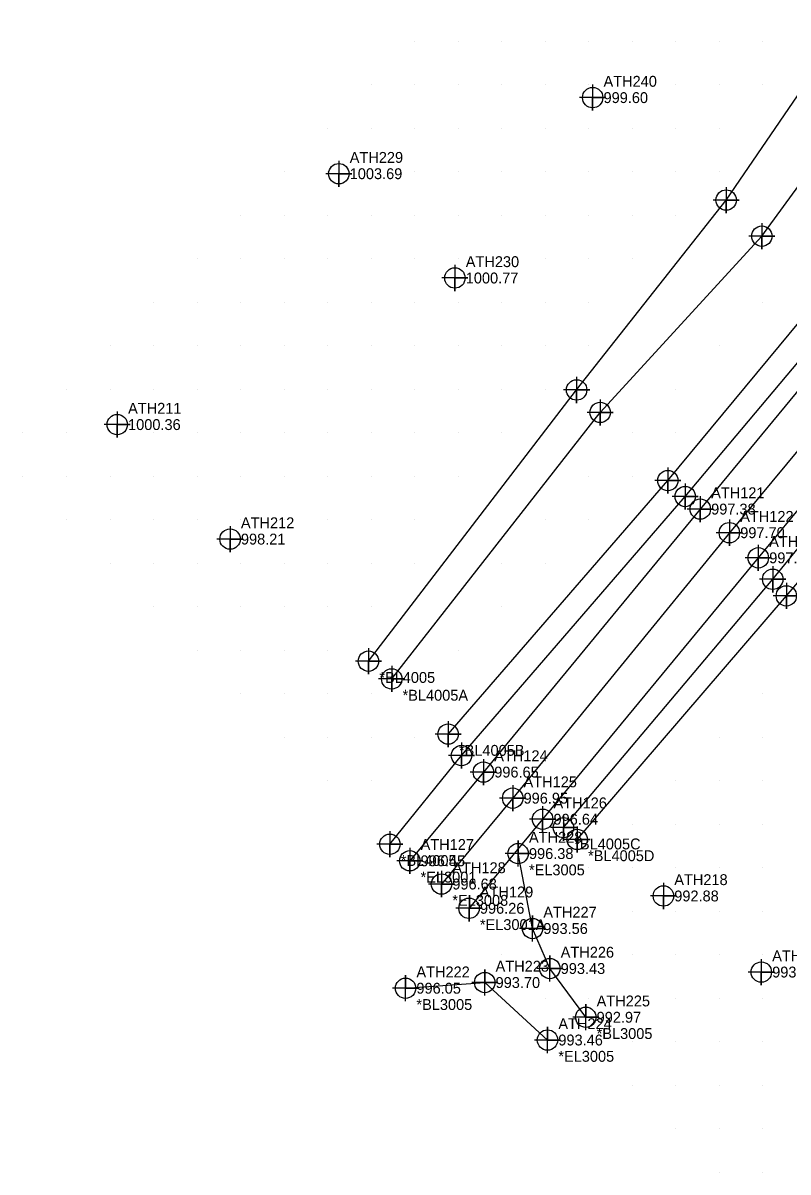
# Model space of a CAD drawing. Extents: x 1116680 to 1117499, y 661040 to 661703.
# Drawn here: x 1116680 to 1116855.8, y 661040 to 661304.2 of the extents above; entities that cross this region are included whole.
import ezdxf

# ---------------------------------------------------------------- set-up
doc = ezdxf.new("R2010")
doc.units = 0
for name, color, linetype in [('Exist DTM Breakline', 7, 'Continuous'), ('Exist DTM Breakline Cogo Comment', 7, 'Continuous'), ('Exist DTM Breakline Cogo Point CELL', 7, 'Continuous'), ('Exist DTM Crownline', 7, 'Continuous'), ('Exist DTM Crownline Cogo Comment', 7, 'Continuous'), ('Exist DTM Crownline Cogo Elevation', 7, 'Continuous'), ('Exist DTM Crownline Cogo Number', 7, 'Continuous'), ('Exist DTM Crownline Cogo Point CELL', 7, 'Continuous'), ('Exist DTM QL2 LIDAR Elevation Point', 7, 'Continuous'), ('Exist DTM Regular Point CELL', 7, 'Continuous'), ('Exist DTM Regular Point Cogo Elevation', 7, 'Continuous'), ('Exist DTM Regular Point Cogo Number', 7, 'Continuous'), ('Exist Roads EOP', 7, 'Continuous'), ('Exist Roads EOP Cogo Comment', 7, 'Continuous'), ('Exist Roads EOP Cogo Elevation', 7, 'Continuous'), ('Exist Roads EOP Cogo Number', 7, 'Continuous'), ('Exist Roads EOP Cogo Point CELL', 7, 'Continuous'), ('Exist Roads Soil', 7, 'Continuous'), ('Exist Roads Soil Cogo Comment', 7, 'Continuous'), ('Exist Roads Soil Cogo Elevation', 7, 'Continuous'), ('Exist Roads Soil Cogo Number', 7, 'Continuous'), ('Exist Roads Soil Cogo Point CELL', 7, 'Continuous')]:
    doc.layers.add(name, color=color, linetype=linetype)

msp = doc.modelspace()

# ---------------------------------------------------------------- linework, layer by layer
at = {"layer": 'Exist DTM Breakline'}
for points in [[(1116759.405, 661157.47), (1116807.255, 661219.832), (1116841.622, 661263.499), (1116875.544, 661313.217), (1116917.082, 661359.208), (1116949.523, 661400.365), (1116973.082, 661430.897), (1117008.611, 661472.228)], [(1116764.746, 661153.381), (1116812.662, 661214.66), (1116849.832, 661255.197), (1116886.132, 661304.973), (1116923.093, 661353.534), (1116959.436, 661397.157), (1116983.43, 661423.245), (1117016.608, 661461.344)], [(1116777.711, 661140.704), (1116828.227, 661198.994), (1116863.907, 661242.056), (1116901.537, 661293.371), (1116942.909, 661337.866), (1116986.207, 661371.481), (1117014.804, 661386.644), (1117027.371, 661386.959)], [(1116764.336, 661115.367), (1116780.79, 661135.76), (1116832.216, 661195.325), (1116868.599, 661238.611), (1116907.746, 661286.411), (1116949.649, 661334.962), (1116977.116, 661358.387), (1117017.083, 661374.758), (1117030.676, 661371.171)], [(1116804.214, 661119.184), (1116852.32, 661176.293), (1116889.45, 661221.661), (1116930.482, 661266.919), (1116979.857, 661313.491), (1117005.659, 661333.608)], [(1116807.384, 661116.479), (1116855.455, 661172.483), (1116887.171, 661209.743), (1116908.403, 661194.399), (1116931.527, 661183.283)]]:
    msp.add_lwpolyline(points, dxfattribs=at)
at = {"layer": 'Exist DTM Breakline Cogo Point CELL'}
for points in [[(1116841.622, 661266.499), (1116841.622, 661260.499), (1116841.622, 661263.499), (1116844.622, 661263.499), (1116838.622, 661263.499)], [(1116849.832, 661258.197), (1116849.832, 661252.197), (1116849.832, 661255.197), (1116852.832, 661255.197), (1116846.832, 661255.197)], [(1116807.255, 661222.832), (1116807.255, 661216.832), (1116807.255, 661219.832), (1116810.255, 661219.832), (1116804.255, 661219.832)], [(1116812.662, 661217.66), (1116812.662, 661211.66), (1116812.662, 661214.66), (1116815.662, 661214.66), (1116809.662, 661214.66)], [(1116828.227, 661201.994), (1116828.227, 661195.994), (1116828.227, 661198.994), (1116831.227, 661198.994), (1116825.227, 661198.994)], [(1116832.216, 661198.325), (1116832.216, 661192.325), (1116832.216, 661195.325), (1116835.216, 661195.325), (1116829.216, 661195.325)], [(1116852.32, 661179.293), (1116852.32, 661173.293), (1116852.32, 661176.293), (1116855.32, 661176.293), (1116849.32, 661176.293)], [(1116855.455, 661175.483), (1116855.455, 661169.483), (1116855.455, 661172.483), (1116858.455, 661172.483), (1116852.455, 661172.483)], [(1116759.405, 661160.47), (1116759.405, 661154.47), (1116759.405, 661157.47), (1116762.405, 661157.47), (1116756.405, 661157.47)], [(1116764.746, 661156.381), (1116764.746, 661150.381), (1116764.746, 661153.381), (1116767.746, 661153.381), (1116761.746, 661153.381)], [(1116777.711, 661143.704), (1116777.711, 661137.704), (1116777.711, 661140.704), (1116780.711, 661140.704), (1116774.711, 661140.704)], [(1116780.79, 661138.76), (1116780.79, 661132.76), (1116780.79, 661135.76), (1116783.79, 661135.76), (1116777.79, 661135.76)], [(1116804.214, 661122.184), (1116804.214, 661116.184), (1116804.214, 661119.184), (1116807.214, 661119.184), (1116801.214, 661119.184)], [(1116764.336, 661118.367), (1116764.336, 661112.367), (1116764.336, 661115.367), (1116767.336, 661115.367), (1116761.336, 661115.367)], [(1116807.384, 661119.479), (1116807.384, 661113.479), (1116807.384, 661116.479), (1116810.384, 661116.479), (1116804.384, 661116.479)]]:
    msp.add_lwpolyline(points, dxfattribs=at)
for centre in [(1116841.622, 661263.499), (1116849.832, 661255.197), (1116807.255, 661219.832), (1116812.662, 661214.66), (1116828.227, 661198.994), (1116832.216, 661195.325), (1116852.32, 661176.293), (1116855.455, 661172.483), (1116759.405, 661157.47), (1116764.746, 661153.381), (1116777.711, 661140.704), (1116780.79, 661135.76), (1116804.214, 661119.184), (1116764.336, 661115.367), (1116807.384, 661116.479)]:
    msp.add_circle(centre, 2.344, dxfattribs=at)
at = {"layer": 'Exist DTM Crownline'}
msp.add_lwpolyline([(1116917.938, 661277.457), (1116878.296, 661230.271), (1116842.354, 661187.006), (1116792.558, 661125.963), (1116776.188, 661106.218)], dxfattribs=at)
at = {"layer": 'Exist DTM Crownline Cogo Point CELL'}
for points in [[(1116842.354, 661190.006), (1116842.354, 661184.006), (1116842.354, 661187.006), (1116845.354, 661187.006), (1116839.354, 661187.006)], [(1116792.558, 661128.963), (1116792.558, 661122.963), (1116792.558, 661125.963), (1116795.558, 661125.963), (1116789.558, 661125.963)], [(1116776.188, 661109.218), (1116776.188, 661103.218), (1116776.188, 661106.218), (1116779.188, 661106.218), (1116773.188, 661106.218)]]:
    msp.add_lwpolyline(points, dxfattribs=at)
for centre in [(1116842.354, 661187.006), (1116792.558, 661125.963), (1116776.188, 661106.218)]:
    msp.add_circle(centre, 2.344, dxfattribs=at)
at = {"layer": 'Exist DTM QL2 LIDAR Elevation Point'}
for p, q in [((1116770, 661300), (1116770, 661300)), ((1116780, 661300), (1116780, 661300)), ((1116790, 661300), (1116790, 661300)), ((1116800, 661300), (1116800, 661300)), ((1116810, 661300), (1116810, 661300)), ((1116820, 661300), (1116820, 661300)), ((1116830, 661300), (1116830, 661300)), ((1116840, 661300), (1116840, 661300)), ((1116850, 661300), (1116850, 661300)), ((1116760, 661290), (1116760, 661290)), ((1116770, 661290), (1116770, 661290)), ((1116780, 661290), (1116780, 661290)), ((1116790, 661290), (1116790, 661290)), ((1116800, 661290), (1116800, 661290)), ((1116810, 661290), (1116810, 661290)), ((1116820, 661290), (1116820, 661290)), ((1116830, 661290), (1116830, 661290)), ((1116840, 661290), (1116840, 661290)), ((1116850, 661290), (1116850, 661290)), ((1116750, 661280), (1116750, 661280)), ((1116760, 661280), (1116760, 661280)), ((1116770, 661280), (1116770, 661280)), ((1116780, 661280), (1116780, 661280)), ((1116790, 661280), (1116790, 661280)), ((1116800, 661280), (1116800, 661280)), ((1116810, 661280), (1116810, 661280)), ((1116820, 661280), (1116820, 661280)), ((1116830, 661280), (1116830, 661280)), ((1116840, 661280), (1116840, 661280)), ((1116740, 661270), (1116740, 661270)), ((1116750, 661270), (1116750, 661270)), ((1116760, 661270), (1116760, 661270)), ((1116770, 661270), (1116770, 661270)), ((1116780, 661270), (1116780, 661270)), ((1116790, 661270), (1116790, 661270)), ((1116800, 661270), (1116800, 661270)), ((1116810, 661270), (1116810, 661270)), ((1116820, 661270), (1116820, 661270)), ((1116830, 661270), (1116830, 661270)), ((1116840, 661270), (1116840, 661270)), ((1116730, 661260), (1116730, 661260)), ((1116740, 661260), (1116740, 661260)), ((1116750, 661260), (1116750, 661260)), ((1116760, 661260), (1116760, 661260)), ((1116770, 661260), (1116770, 661260)), ((1116780, 661260), (1116780, 661260)), ((1116790, 661260), (1116790, 661260)), ((1116800, 661260), (1116800, 661260)), ((1116810, 661260), (1116810, 661260)), ((1116820, 661260), (1116820, 661260)), ((1116830, 661260), (1116830, 661260)), ((1116720, 661250), (1116720, 661250)), ((1116730, 661250), (1116730, 661250)), ((1116740, 661250), (1116740, 661250)), ((1116750, 661250), (1116750, 661250)), ((1116760, 661250), (1116760, 661250)), ((1116770, 661250), (1116770, 661250)), ((1116780, 661250), (1116780, 661250)), ((1116790, 661250), (1116790, 661250)), ((1116800, 661250), (1116800, 661250)), ((1116810, 661250), (1116810, 661250)), ((1116820, 661250), (1116820, 661250)), ((1116710, 661240), (1116710, 661240)), ((1116720, 661240), (1116720, 661240)), ((1116730, 661240), (1116730, 661240)), ((1116740, 661240), (1116740, 661240)), ((1116750, 661240), (1116750, 661240)), ((1116760, 661240), (1116760, 661240)), ((1116770, 661240), (1116770, 661240)), ((1116780, 661240), (1116780, 661240)), ((1116790, 661240), (1116790, 661240)), ((1116800, 661240), (1116800, 661240)), ((1116810, 661240), (1116810, 661240)), ((1116850, 661240), (1116850, 661240)), ((1116700, 661230), (1116700, 661230)), ((1116710, 661230), (1116710, 661230)), ((1116720, 661230), (1116720, 661230)), ((1116730, 661230), (1116730, 661230)), ((1116740, 661230), (1116740, 661230)), ((1116750, 661230), (1116750, 661230)), ((1116760, 661230), (1116760, 661230)), ((1116770, 661230), (1116770, 661230)), ((1116780, 661230), (1116780, 661230)), ((1116790, 661230), (1116790, 661230)), ((1116800, 661230), (1116800, 661230)), ((1116810, 661230), (1116810, 661230)), ((1116840, 661230), (1116840, 661230)), ((1116690, 661220), (1116690, 661220)), ((1116700, 661220), (1116700, 661220)), ((1116710, 661220), (1116710, 661220)), ((1116720, 661220), (1116720, 661220)), ((1116730, 661220), (1116730, 661220)), ((1116740, 661220), (1116740, 661220)), ((1116750, 661220), (1116750, 661220)), ((1116760, 661220), (1116760, 661220)), ((1116770, 661220), (1116770, 661220)), ((1116780, 661220), (1116780, 661220)), ((1116790, 661220), (1116790, 661220)), ((1116800, 661220), (1116800, 661220)), ((1116830, 661220), (1116830, 661220)), ((1116680, 661210), (1116680, 661210)), ((1116690, 661210), (1116690, 661210)), ((1116710, 661210), (1116710, 661210)), ((1116720, 661210), (1116720, 661210)), ((1116730, 661210), (1116730, 661210)), ((1116740, 661210), (1116740, 661210)), ((1116750, 661210), (1116750, 661210)), ((1116760, 661210), (1116760, 661210)), ((1116770, 661210), (1116770, 661210)), ((1116780, 661210), (1116780, 661210)), ((1116790, 661210), (1116790, 661210)), ((1116820, 661210), (1116820, 661210)), ((1116830, 661210), (1116830, 661210)), ((1116680, 661200), (1116680, 661200)), ((1116690, 661200), (1116690, 661200)), ((1116700, 661200), (1116700, 661200)), ((1116710, 661200), (1116710, 661200)), ((1116720, 661200), (1116720, 661200)), ((1116730, 661200), (1116730, 661200)), ((1116740, 661200), (1116740, 661200)), ((1116750, 661200), (1116750, 661200)), ((1116760, 661200), (1116760, 661200)), ((1116770, 661200), (1116770, 661200)), ((1116780, 661200), (1116780, 661200)), ((1116810, 661200), (1116810, 661200)), ((1116820, 661200), (1116820, 661200)), ((1116690, 661190), (1116690, 661190)), ((1116700, 661190), (1116700, 661190)), ((1116710, 661190), (1116710, 661190)), ((1116720, 661190), (1116720, 661190)), ((1116730, 661190), (1116730, 661190)), ((1116740, 661190), (1116740, 661190)), ((1116750, 661190), (1116750, 661190)), ((1116760, 661190), (1116760, 661190)), ((1116770, 661190), (1116770, 661190)), ((1116800, 661190), (1116800, 661190)), ((1116810, 661190), (1116810, 661190)), ((1116700, 661180), (1116700, 661180)), ((1116710, 661180), (1116710, 661180)), ((1116720, 661180), (1116720, 661180)), ((1116730, 661180), (1116730, 661180)), ((1116740, 661180), (1116740, 661180)), ((1116750, 661180), (1116750, 661180)), ((1116760, 661180), (1116760, 661180)), ((1116770, 661180), (1116770, 661180)), ((1116790, 661180), (1116790, 661180)), ((1116800, 661180), (1116800, 661180)), ((1116710, 661170), (1116710, 661170)), ((1116720, 661170), (1116720, 661170)), ((1116730, 661170), (1116730, 661170)), ((1116740, 661170), (1116740, 661170)), ((1116750, 661170), (1116750, 661170)), ((1116760, 661170), (1116760, 661170)), ((1116790, 661170), (1116790, 661170)), ((1116720, 661160), (1116720, 661160)), ((1116730, 661160), (1116730, 661160)), ((1116740, 661160), (1116740, 661160)), ((1116750, 661160), (1116750, 661160)), ((1116780, 661160), (1116780, 661160)), ((1116730, 661150), (1116730, 661150)), ((1116740, 661150), (1116740, 661150)), ((1116750, 661150), (1116750, 661150)), ((1116760, 661150), (1116760, 661150)), ((1116770, 661150), (1116770, 661150)), ((1116780, 661150), (1116780, 661150)), ((1116850, 661150), (1116850, 661150)), ((1116740, 661140), (1116740, 661140)), ((1116750, 661140), (1116750, 661140)), ((1116760, 661140), (1116760, 661140)), ((1116770, 661140), (1116770, 661140)), ((1116840, 661140), (1116840, 661140)), ((1116850, 661140), (1116850, 661140)), ((1116750, 661130), (1116750, 661130)), ((1116760, 661130), (1116760, 661130)), ((1116830, 661130), (1116830, 661130)), ((1116840, 661130), (1116840, 661130)), ((1116850, 661130), (1116850, 661130)), ((1116820, 661120), (1116820, 661120)), ((1116830, 661120), (1116830, 661120)), ((1116840, 661120), (1116840, 661120)), ((1116850, 661120), (1116850, 661120)), ((1116810, 661110), (1116810, 661110)), ((1116820, 661110), (1116820, 661110)), ((1116830, 661110), (1116830, 661110)), ((1116840, 661110), (1116840, 661110)), ((1116850, 661110), (1116850, 661110)), ((1116800, 661100), (1116800, 661100)), ((1116810, 661100), (1116810, 661100)), ((1116820, 661100), (1116820, 661100)), ((1116830, 661100), (1116830, 661100)), ((1116840, 661100), (1116840, 661100)), ((1116850, 661100), (1116850, 661100)), ((1116790, 661090), (1116790, 661090)), ((1116810, 661090), (1116810, 661090)), ((1116820, 661090), (1116820, 661090)), ((1116830, 661090), (1116830, 661090)), ((1116840, 661090), (1116840, 661090)), ((1116850, 661090), (1116850, 661090)), ((1116800, 661080), (1116800, 661080)), ((1116810, 661080), (1116810, 661080)), ((1116820, 661080), (1116820, 661080)), ((1116830, 661080), (1116830, 661080)), ((1116840, 661080), (1116840, 661080)), ((1116850, 661080), (1116850, 661080)), ((1116810, 661070), (1116810, 661070)), ((1116820, 661070), (1116820, 661070)), ((1116830, 661070), (1116830, 661070)), ((1116840, 661070), (1116840, 661070)), ((1116850, 661070), (1116850, 661070)), ((1116820, 661060), (1116820, 661060)), ((1116830, 661060), (1116830, 661060)), ((1116840, 661060), (1116840, 661060)), ((1116850, 661060), (1116850, 661060)), ((1116830, 661050), (1116830, 661050)), ((1116840, 661050), (1116840, 661050)), ((1116850, 661050), (1116850, 661050)), ((1116840, 661040), (1116840, 661040)), ((1116850, 661040), (1116850, 661040))]:
    msp.add_line(p, q, dxfattribs=at)
at = {"layer": 'Exist DTM Regular Point CELL'}
for points in [[(1116810.938, 661290.054), (1116810.938, 661284.054), (1116810.938, 661287.054), (1116813.938, 661287.054), (1116807.938, 661287.054)], [(1116752.6, 661272.555), (1116752.6, 661266.555), (1116752.6, 661269.555), (1116755.6, 661269.555), (1116749.6, 661269.555)], [(1116779.273, 661248.579), (1116779.273, 661242.579), (1116779.273, 661245.579), (1116782.273, 661245.579), (1116776.273, 661245.579)], [(1116701.657, 661214.869), (1116701.657, 661208.869), (1116701.657, 661211.869), (1116704.657, 661211.869), (1116698.657, 661211.869)], [(1116727.593, 661188.538), (1116727.593, 661182.538), (1116727.593, 661185.538), (1116730.593, 661185.538), (1116724.593, 661185.538)], [(1116827.197, 661106.474), (1116827.197, 661100.474), (1116827.197, 661103.474), (1116830.197, 661103.474), (1116824.197, 661103.474)], [(1116849.702, 661088.978), (1116849.702, 661082.978), (1116849.702, 661085.978), (1116852.702, 661085.978), (1116846.702, 661085.978)]]:
    msp.add_lwpolyline(points, dxfattribs=at)
for centre in [(1116810.938, 661287.054), (1116752.6, 661269.555), (1116779.273, 661245.579), (1116701.657, 661211.869), (1116727.593, 661185.538), (1116827.197, 661103.474), (1116849.702, 661085.978)]:
    msp.add_circle(centre, 2.344, dxfattribs=at)
at = {"layer": 'Exist Roads EOP'}
for points in [[(1116925.984, 661301.817), (1116910.969, 661283.553), (1116871.822, 661236.252), (1116835.673, 661192.44), (1116785.819, 661131.962), (1116768.893, 661111.563)], [(1116924.898, 661271.684), (1116885.096, 661224.926), (1116849.016, 661181.231), (1116799.444, 661121.119), (1116782.519, 661100.642)]]:
    msp.add_lwpolyline(points, dxfattribs=at)
at = {"layer": 'Exist Roads EOP Cogo Point CELL'}
for points in [[(1116835.673, 661195.44), (1116835.673, 661189.44), (1116835.673, 661192.44), (1116838.673, 661192.44), (1116832.673, 661192.44)], [(1116849.016, 661184.231), (1116849.016, 661178.231), (1116849.016, 661181.231), (1116852.016, 661181.231), (1116846.016, 661181.231)], [(1116785.819, 661134.962), (1116785.819, 661128.962), (1116785.819, 661131.962), (1116788.819, 661131.962), (1116782.819, 661131.962)], [(1116799.444, 661124.119), (1116799.444, 661118.119), (1116799.444, 661121.119), (1116802.444, 661121.119), (1116796.444, 661121.119)], [(1116768.893, 661114.563), (1116768.893, 661108.563), (1116768.893, 661111.563), (1116771.893, 661111.563), (1116765.893, 661111.563)], [(1116782.519, 661103.642), (1116782.519, 661097.642), (1116782.519, 661100.642), (1116785.519, 661100.642), (1116779.519, 661100.642)]]:
    msp.add_lwpolyline(points, dxfattribs=at)
for centre in [(1116835.673, 661192.44), (1116849.016, 661181.231), (1116785.819, 661131.962), (1116799.444, 661121.119), (1116768.893, 661111.563), (1116782.519, 661100.642)]:
    msp.add_circle(centre, 2.344, dxfattribs=at)
at = {"layer": 'Exist Roads Soil'}
for points in [[(1116809.354, 661075.585), (1116801.092, 661086.79), (1116797.101, 661095.987), (1116793.802, 661113.223)], [(1116767.931, 661082.26), (1116786.129, 661083.571), (1116800.554, 661070.352)]]:
    msp.add_lwpolyline(points, dxfattribs=at)
at = {"layer": 'Exist Roads Soil Cogo Point CELL'}
for points in [[(1116793.802, 661110.223), (1116793.802, 661116.223), (1116793.802, 661113.223), (1116796.802, 661113.223), (1116790.802, 661113.223)], [(1116797.101, 661092.987), (1116797.101, 661098.987), (1116797.101, 661095.987), (1116800.101, 661095.987), (1116794.101, 661095.987)], [(1116801.092, 661083.79), (1116801.092, 661089.79), (1116801.092, 661086.79), (1116804.092, 661086.79), (1116798.092, 661086.79)], [(1116786.129, 661080.571), (1116786.129, 661086.571), (1116786.129, 661083.571), (1116789.129, 661083.571), (1116783.129, 661083.571)], [(1116767.931, 661079.26), (1116767.931, 661085.26), (1116767.931, 661082.26), (1116770.931, 661082.26), (1116764.931, 661082.26)], [(1116809.354, 661072.585), (1116809.354, 661078.585), (1116809.354, 661075.585), (1116812.354, 661075.585), (1116806.354, 661075.585)], [(1116800.554, 661067.352), (1116800.554, 661073.352), (1116800.554, 661070.352), (1116803.554, 661070.352), (1116797.554, 661070.352)]]:
    msp.add_lwpolyline(points, dxfattribs=at)
for centre in [(1116793.802, 661113.223), (1116797.101, 661095.987), (1116801.092, 661086.79), (1116786.129, 661083.571), (1116767.931, 661082.26), (1116809.354, 661075.585), (1116800.554, 661070.352)]:
    msp.add_circle(centre, 2.344, dxfattribs=at)

# ---------------------------------------------------------------- texts
at = {"layer": 'Exist DTM Breakline Cogo Comment'}
for s, p in [('*BL4005', (1116761.905, 661152.47)), ('*BL4005A', (1116767.246, 661148.381)), ('*BL4005B', (1116780.211, 661135.704)), ('*BL4005C', (1116806.714, 661114.184)), ('*BL4005', (1116766.836, 661110.367)), ('*BL4005D', (1116809.884, 661111.479))]:
    msp.add_text(s, height=2.5, dxfattribs=at).set_placement(p)
at = {"layer": 'Exist DTM Crownline Cogo Comment'}
msp.add_text('*EL3008', height=2.5, dxfattribs=at).set_placement((1116778.688, 661101.218))
at = {"layer": 'Exist DTM Crownline Cogo Elevation'}
for s, p in [('997.70', (1116844.854, 661185.756)), ('996.95', (1116795.058, 661124.713)), ('996.68', (1116778.688, 661104.968))]:
    msp.add_text(s, height=2.5, dxfattribs=at).set_placement(p)
at = {"layer": 'Exist DTM Crownline Cogo Number'}
for s, p in [('ATH122', (1116844.854, 661189.506)), ('ATH125', (1116795.058, 661128.463)), ('ATH128', (1116778.688, 661108.718))]:
    msp.add_text(s, height=2.5, dxfattribs=at).set_placement(p)
at = {"layer": 'Exist DTM Regular Point Cogo Elevation'}
for s, p in [('999.60', (1116813.438, 661285.804)), ('1003.69', (1116755.1, 661268.305)), ('1000.77', (1116781.773, 661244.329)), ('1000.36', (1116704.157, 661210.619)), ('998.21', (1116730.093, 661184.288)), ('992.88', (1116829.697, 661102.224)), ('993.49', (1116852.202, 661084.728))]:
    msp.add_text(s, height=2.5, dxfattribs=at).set_placement(p)
at = {"layer": 'Exist DTM Regular Point Cogo Number'}
for s, p in [('ATH240', (1116813.438, 661289.554)), ('ATH229', (1116755.1, 661272.055)), ('ATH230', (1116781.773, 661248.079)), ('ATH211', (1116704.157, 661214.369)), ('ATH212', (1116730.093, 661188.038)), ('ATH218', (1116829.697, 661105.974)), ('ATH219', (1116852.202, 661088.478))]:
    msp.add_text(s, height=2.5, dxfattribs=at).set_placement(p)
at = {"layer": 'Exist Roads EOP Cogo Comment'}
for s, p in [('*EL3001', (1116771.393, 661106.563)), ('*EL3001A', (1116785.019, 661095.642))]:
    msp.add_text(s, height=2.5, dxfattribs=at).set_placement(p)
at = {"layer": 'Exist Roads EOP Cogo Elevation'}
for s, p in [('997.38', (1116838.173, 661191.19)), ('997.37', (1116851.516, 661179.981)), ('996.65', (1116788.319, 661130.712)), ('996.64', (1116801.944, 661119.869)), ('996.45', (1116771.393, 661110.313)), ('996.26', (1116785.019, 661099.392))]:
    msp.add_text(s, height=2.5, dxfattribs=at).set_placement(p)
at = {"layer": 'Exist Roads EOP Cogo Number'}
for s, p in [('ATH121', (1116838.173, 661194.94)), ('ATH123', (1116851.516, 661183.731)), ('ATH124', (1116788.319, 661134.462)), ('ATH126', (1116801.944, 661123.619)), ('ATH127', (1116771.393, 661114.063)), ('ATH129', (1116785.019, 661103.142))]:
    msp.add_text(s, height=2.5, dxfattribs=at).set_placement(p)
at = {"layer": 'Exist Roads Soil Cogo Comment'}
for s, p in [('*EL3005', (1116796.302, 661108.223)), ('*BL3005', (1116770.431, 661077.26)), ('*BL3005', (1116811.854, 661070.585)), ('*EL3005', (1116803.054, 661065.352))]:
    msp.add_text(s, height=2.5, dxfattribs=at).set_placement(p)
at = {"layer": 'Exist Roads Soil Cogo Elevation'}
for s, p in [('996.38', (1116796.302, 661111.973)), ('993.56', (1116799.601, 661094.737)), ('993.43', (1116803.592, 661085.54)), ('996.05', (1116770.431, 661081.01)), ('993.70', (1116788.629, 661082.321)), ('992.97', (1116811.854, 661074.335)), ('993.46', (1116803.054, 661069.102))]:
    msp.add_text(s, height=2.5, dxfattribs=at).set_placement(p)
at = {"layer": 'Exist Roads Soil Cogo Number'}
for s, p in [('ATH228', (1116796.302, 661115.723)), ('ATH227', (1116799.601, 661098.487)), ('ATH226', (1116803.592, 661089.29)), ('ATH223', (1116788.629, 661086.071)), ('ATH222', (1116770.431, 661084.76)), ('ATH225', (1116811.854, 661078.085)), ('ATH224', (1116803.054, 661072.852))]:
    msp.add_text(s, height=2.5, dxfattribs=at).set_placement(p)

doc.saveas('drawing.dxf')
